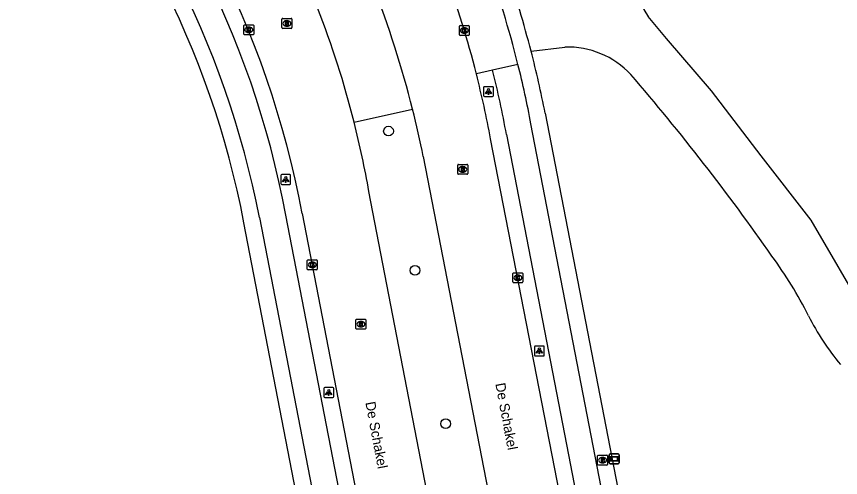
# Model space of a CAD drawing. Extents: x 156141 to 158132, y 385651 to 388399.
# Drawn here: x 156763.2 to 156845.9, y 386839.7 to 386886.1 of the extents above; entities that cross this region are included whole.
import ezdxf

# ---------------------------------------------------------------- set-up
doc = ezdxf.new("R2010")
doc.units = 0
for name, color, linetype in [('IMGEO_Boom', 7, 'Continuous'), ('IMGEO_Brandkraan', 7, 'Continuous'), ('IMGEO_Fietspad_gesloten', 7, 'Continuous'), ('IMGEO_Kolk', 7, 'Continuous'), ('IMGEO_Lichtpunt', 7, 'Continuous'), ('IMGEO_Openbare_ruimte_label', 7, 'Continuous'), ('IMGEO_Rijbaan_lokaal_gesloten', 7, 'Continuous'), ('IMGEO_Rijbaan_lokaal_open', 7, 'Continuous'), ('IMGEO_Rioolput', 7, 'Continuous'), ('IMGEO_Verklikker', 7, 'Continuous'), ('IMGEO_Voetpad_open', 7, 'Continuous')]:
    doc.layers.add(name, color=color, linetype=linetype)

msp = doc.modelspace()

# ---------------------------------------------------------------- linework, layer by layer
at = {"layer": 'IMGEO_Boom'}
for centre in [(156800.541, 386874.566), (156803.195, 386860.57), (156806.282, 386845.15)]:
    msp.add_circle(centre, 0.489, dxfattribs=at)
at = {"layer": 'IMGEO_Brandkraan'}
for p, q in [((156821.54, 386841.068), (156821.54, 386841.92)), ((156821.615, 386841.994), (156822.467, 386841.994)), ((156822.028, 386841.774), (156822.053, 386841.774)), ((156822.541, 386841.92), (156822.541, 386841.068)), ((156822.467, 386840.994), (156821.615, 386840.994)), ((156822.051, 386841.214), (156822.026, 386841.214))]:
    msp.add_line(p, q, dxfattribs=at)
for points in [[(156821.54, 386841.068), (156821.54, 386841.92)], [(156821.615, 386841.994), (156822.467, 386841.994)], [(156821.888, 386841.694), (156821.888, 386841.294), (156822.101, 386841.294)], [(156822.119, 386841.694), (156821.888, 386841.694)], [(156822.067, 386841.613), (156822.013, 386841.613), (156822.013, 386841.537)], [(156822.013, 386841.537), (156822.066, 386841.537)], [(156822.541, 386841.92), (156822.541, 386841.068)], [(156822.467, 386840.994), (156821.615, 386840.994)], [(156822.075, 386841.461), (156822.013, 386841.461), (156822.013, 386841.38)], [(156822.013, 386841.38), (156822.075, 386841.38)]]:
    msp.add_lwpolyline(points, dxfattribs=at)
for centre, radius, start, end in [((156821.617, 386841.918), 0.0765, 91.55205, 178.44795), ((156821.617, 386841.918), 0.0765, 91.55205, 178.44795), ((156822.068, 386841.575), 0.0379, 267.82845, 90.93552), ((156822.123, 386841.549), 0.145, 59.4692, 91.53667), ((156822.148, 386841.596), 0.0922, 285.51372, 58.15012), ((156822.153, 386841.404), 0.105, 301.31148, 78.98903), ((156822.465, 386841.918), 0.0765, 1.55205, 88.44795), ((156822.465, 386841.918), 0.0765, 1.55205, 88.44795), ((156821.617, 386841.07), 0.0765, 181.55205, 268.44795), ((156821.617, 386841.07), 0.0765, 181.55205, 268.44795), ((156822.076, 386841.42), 0.0404, 269.87594, 90.50774), ((156822.107, 386841.545), 0.251, 268.66757, 293.53466), ((156822.465, 386841.07), 0.0765, 271.55205, 358.44795), ((156822.465, 386841.07), 0.0765, 271.55205, 358.44795)]:
    msp.add_arc(centre, radius, start, end, dxfattribs=at)
for centre, major_axis, ratio, start_param, end_param in [((156822.027, 386841.494), (-0.387, 0.002), 0.722429, 4.712389, 7.853982), ((156822.052, 386841.494), (-0.39, 0.002), 0.717154, 1.570796, 4.712389)]:
    msp.add_ellipse(centre, major_axis=major_axis, ratio=ratio, start_param=start_param, end_param=end_param, dxfattribs=at)
at = {"layer": 'IMGEO_Fietspad_gesloten'}
for points in [[(156831.327, 386790.024), (156827.767, 386808.488), (156814.851, 386875.299)], [(156812.389, 386874.233), (156825.217, 386807.909)], [(156787.566, 386865.893), (156800.014, 386801.586)], [(156802.323, 386803.676), (156790.238, 386866.122)]]:
    msp.add_lwpolyline(points, dxfattribs=at)
for centre, radius, start, end in [((156697.735, 386848.719), 94.126, 10.65483, 44.23031), ((156696.985, 386848.39), 92.256, 10.93627, 43.98113), ((156711.691, 386855.855), 104.977, 10.67398, 14.01163), ((156710.398, 386855.539), 103.69, 10.38669, 14.03443)]:
    msp.add_arc(centre, radius, start, end, dxfattribs=at)
at = {"layer": 'IMGEO_Kolk'}
for p, q in [((156786.008, 386884.32), (156786.008, 386885.172)), ((156786.083, 386885.246), (156786.935, 386885.246)), ((156786.496, 386885.026), (156786.521, 386885.026)), ((156787.009, 386885.172), (156787.009, 386884.32)), ((156807.654, 386884.252), (156807.654, 386885.104)), ((156807.729, 386885.178), (156808.581, 386885.178)), ((156808.142, 386884.958), (156808.167, 386884.958)), ((156808.655, 386885.104), (156808.655, 386884.252)), ((156786.935, 386884.246), (156786.083, 386884.246)), ((156786.519, 386884.466), (156786.494, 386884.466)), ((156808.581, 386884.178), (156807.729, 386884.178)), ((156808.165, 386884.398), (156808.14, 386884.398)), ((156792.385, 386860.705), (156792.385, 386861.557)), ((156792.46, 386861.631), (156793.312, 386861.631)), ((156792.873, 386861.411), (156792.898, 386861.411)), ((156793.386, 386861.557), (156793.386, 386860.705)), ((156793.312, 386860.631), (156792.46, 386860.631)), ((156792.896, 386860.851), (156792.871, 386860.851)), ((156813.032, 386859.401), (156813.032, 386860.253)), ((156813.107, 386860.327), (156813.959, 386860.327)), ((156813.52, 386860.107), (156813.545, 386860.107)), ((156814.033, 386860.253), (156814.033, 386859.401)), ((156813.959, 386859.327), (156813.107, 386859.327)), ((156813.543, 386859.547), (156813.518, 386859.547))]:
    msp.add_line(p, q, dxfattribs=at)
for points in [[(156786.008, 386884.32), (156786.008, 386885.172)], [(156786.083, 386885.246), (156786.935, 386885.246)], [(156786.329, 386884.946), (156786.452, 386884.946), (156786.452, 386884.795), (156786.582, 386884.946), (156786.746, 386884.946), (156786.6, 386884.795), (156786.753, 386884.546), (156786.601, 386884.546), (156786.516, 386884.71), (156786.452, 386884.643), (156786.452, 386884.546), (156786.329, 386884.546), (156786.329, 386884.946)], [(156787.009, 386885.172), (156787.009, 386884.32)], [(156807.654, 386884.252), (156807.654, 386885.104)], [(156807.729, 386885.178), (156808.581, 386885.178)], [(156807.975, 386884.878), (156808.098, 386884.878), (156808.098, 386884.727), (156808.228, 386884.878), (156808.392, 386884.878), (156808.246, 386884.727), (156808.399, 386884.478), (156808.247, 386884.478), (156808.162, 386884.642), (156808.098, 386884.575), (156808.098, 386884.478), (156807.975, 386884.478), (156807.975, 386884.878)], [(156808.655, 386885.104), (156808.655, 386884.252)], [(156786.935, 386884.246), (156786.083, 386884.246)], [(156808.581, 386884.178), (156807.729, 386884.178)], [(156792.385, 386860.705), (156792.385, 386861.557)], [(156792.46, 386861.631), (156793.312, 386861.631)], [(156793.386, 386861.557), (156793.386, 386860.705)], [(156793.312, 386860.631), (156792.46, 386860.631)], [(156792.706, 386861.331), (156792.829, 386861.331), (156792.829, 386861.18), (156792.959, 386861.331), (156793.123, 386861.331), (156792.977, 386861.18), (156793.13, 386860.931), (156792.978, 386860.931), (156792.893, 386861.095), (156792.829, 386861.028), (156792.829, 386860.931), (156792.706, 386860.931), (156792.706, 386861.331)], [(156813.032, 386859.401), (156813.032, 386860.253)], [(156813.107, 386860.327), (156813.959, 386860.327)], [(156813.353, 386860.027), (156813.476, 386860.027), (156813.476, 386859.876), (156813.606, 386860.027), (156813.77, 386860.027), (156813.624, 386859.876), (156813.777, 386859.627), (156813.625, 386859.627), (156813.54, 386859.791), (156813.476, 386859.724), (156813.476, 386859.627), (156813.353, 386859.627), (156813.353, 386860.027)], [(156814.033, 386860.253), (156814.033, 386859.401)], [(156813.959, 386859.327), (156813.107, 386859.327)]]:
    msp.add_lwpolyline(points, dxfattribs=at)
for centre, start, end in [((156786.085, 386885.17), 91.55205, 178.44795), ((156786.085, 386885.17), 91.55205, 178.44795), ((156786.933, 386885.17), 1.55205, 88.44795), ((156786.933, 386885.17), 1.55205, 88.44795), ((156807.731, 386885.102), 91.55205, 178.44795), ((156807.731, 386885.102), 91.55205, 178.44795), ((156808.579, 386885.102), 1.55205, 88.44795), ((156808.579, 386885.102), 1.55205, 88.44795), ((156786.085, 386884.322), 181.55205, 268.44795), ((156786.085, 386884.322), 181.55205, 268.44795), ((156786.933, 386884.322), 271.55205, 358.44795), ((156786.933, 386884.322), 271.55205, 358.44795), ((156807.731, 386884.254), 181.55205, 268.44795), ((156807.731, 386884.254), 181.55205, 268.44795), ((156808.579, 386884.254), 271.55205, 358.44795), ((156808.579, 386884.254), 271.55205, 358.44795), ((156792.462, 386861.555), 91.55205, 178.44795), ((156792.462, 386861.555), 91.55205, 178.44795), ((156793.31, 386861.555), 1.55205, 88.44795), ((156793.31, 386861.555), 1.55205, 88.44795), ((156792.462, 386860.707), 181.55205, 268.44795), ((156792.462, 386860.707), 181.55205, 268.44795), ((156793.31, 386860.707), 271.55205, 358.44795), ((156793.31, 386860.707), 271.55205, 358.44795), ((156813.109, 386860.251), 91.55205, 178.44795), ((156813.109, 386860.251), 91.55205, 178.44795), ((156813.957, 386860.251), 1.55205, 88.44795), ((156813.957, 386860.251), 1.55205, 88.44795), ((156813.109, 386859.403), 181.55205, 268.44795), ((156813.109, 386859.403), 181.55205, 268.44795), ((156813.957, 386859.403), 271.55205, 358.44795), ((156813.957, 386859.403), 271.55205, 358.44795)]:
    msp.add_arc(centre, 0.0765, start, end, dxfattribs=at)
for centre, major_axis, ratio, start_param, end_param in [((156786.495, 386884.746), (-0.387, 0.002), 0.722429, 4.712389, 7.853982), ((156786.52, 386884.746), (-0.39, 0.002), 0.717154, 1.570796, 4.712389), ((156808.141, 386884.678), (-0.387, 0.002), 0.722429, 4.712389, 7.853982), ((156808.166, 386884.678), (-0.39, 0.002), 0.717154, 1.570796, 4.712389), ((156792.872, 386861.131), (-0.387, 0.002), 0.722429, 4.712389, 7.853982), ((156792.897, 386861.131), (-0.39, 0.002), 0.717154, 1.570796, 4.712389), ((156813.519, 386859.827), (-0.387, 0.002), 0.722429, 4.712389, 7.853982), ((156813.544, 386859.827), (-0.39, 0.002), 0.717154, 1.570796, 4.712389)]:
    msp.add_ellipse(centre, major_axis=major_axis, ratio=ratio, start_param=start_param, end_param=end_param, dxfattribs=at)
at = {"layer": 'IMGEO_Lichtpunt'}
for p, q in [((156810.085, 386878.94), (156810.085, 386878.133)), ((156810.085, 386878.94), (156810.085, 386878.133)), ((156810.987, 386879.035), (156810.179, 386879.035)), ((156810.987, 386879.035), (156810.179, 386879.035)), ((156811.081, 386878.133), (156811.081, 386878.94)), ((156811.081, 386878.133), (156811.081, 386878.94)), ((156810.179, 386878.039), (156810.987, 386878.039)), ((156810.179, 386878.039), (156810.987, 386878.039)), ((156789.714, 386870.102), (156789.714, 386869.295)), ((156789.714, 386870.102), (156789.714, 386869.295)), ((156790.616, 386870.197), (156789.808, 386870.197)), ((156790.616, 386870.197), (156789.808, 386870.197)), ((156790.71, 386869.295), (156790.71, 386870.102)), ((156790.71, 386869.295), (156790.71, 386870.102)), ((156789.808, 386869.201), (156790.616, 386869.201)), ((156789.808, 386869.201), (156790.616, 386869.201)), ((156815.193, 386852.869), (156815.193, 386852.062)), ((156815.193, 386852.869), (156815.193, 386852.062)), ((156816.095, 386852.964), (156815.287, 386852.964)), ((156816.095, 386852.964), (156815.287, 386852.964)), ((156816.189, 386852.062), (156816.189, 386852.869)), ((156816.189, 386852.062), (156816.189, 386852.869)), ((156815.287, 386851.968), (156816.095, 386851.968)), ((156815.287, 386851.968), (156816.095, 386851.968)), ((156794.038, 386848.696), (156794.038, 386847.889)), ((156794.038, 386848.696), (156794.038, 386847.889)), ((156794.94, 386848.791), (156794.132, 386848.791)), ((156794.94, 386848.791), (156794.132, 386848.791)), ((156795.034, 386847.889), (156795.034, 386848.696)), ((156795.034, 386847.889), (156795.034, 386848.696)), ((156794.132, 386847.795), (156794.94, 386847.795)), ((156794.132, 386847.795), (156794.94, 386847.795))]:
    msp.add_line(p, q, dxfattribs=at)
for points in [[(156810.459, 386878.604), (156810.498, 386878.576), (156810.31, 386878.314), (156810.272, 386878.341), (156810.459, 386878.604)], [(156810.561, 386878.556), (156810.608, 386878.556), (156810.608, 386878.234), (156810.561, 386878.234), (156810.561, 386878.556)], [(156810.671, 386878.576), (156810.709, 386878.603), (156810.896, 386878.341), (156810.857, 386878.313), (156810.671, 386878.576)], [(156790.088, 386869.766), (156790.127, 386869.738), (156789.939, 386869.476), (156789.901, 386869.503), (156790.088, 386869.766)], [(156790.19, 386869.718), (156790.237, 386869.718), (156790.237, 386869.396), (156790.19, 386869.396), (156790.19, 386869.718)], [(156790.3, 386869.738), (156790.338, 386869.765), (156790.525, 386869.503), (156790.486, 386869.475), (156790.3, 386869.738)], [(156815.567, 386852.533), (156815.606, 386852.505), (156815.418, 386852.243), (156815.38, 386852.27), (156815.567, 386852.533)], [(156815.669, 386852.485), (156815.716, 386852.485), (156815.716, 386852.163), (156815.669, 386852.163), (156815.669, 386852.485)], [(156815.779, 386852.505), (156815.817, 386852.532), (156816.004, 386852.27), (156815.965, 386852.242), (156815.779, 386852.505)], [(156794.412, 386848.36), (156794.451, 386848.332), (156794.263, 386848.07), (156794.225, 386848.097), (156794.412, 386848.36)], [(156794.514, 386848.312), (156794.561, 386848.312), (156794.561, 386847.99), (156794.514, 386847.99), (156794.514, 386848.312)], [(156794.624, 386848.332), (156794.662, 386848.359), (156794.849, 386848.097), (156794.81, 386848.069), (156794.624, 386848.332)]]:
    msp.add_lwpolyline(points, dxfattribs=at)
for centre in [(156810.584, 386878.738), (156790.213, 386869.9), (156815.692, 386852.667), (156794.537, 386848.494)]:
    msp.add_circle(centre, 0.0994, dxfattribs=at)
for centre, start, end in [((156810.179, 386878.94), 90, 180), ((156810.179, 386878.94), 90, 180), ((156810.987, 386878.94), 0, 90), ((156810.987, 386878.94), 0, 90), ((156810.179, 386878.133), 180, 270), ((156810.179, 386878.133), 180, 270), ((156810.987, 386878.133), 270, 0), ((156810.987, 386878.133), 270, 360), ((156789.808, 386870.102), 90, 180), ((156789.808, 386870.102), 90, 180), ((156790.616, 386870.102), 0, 90), ((156790.616, 386870.102), 0, 90), ((156789.808, 386869.295), 180, 270), ((156789.808, 386869.295), 180, 270), ((156790.616, 386869.295), 270, 0), ((156790.616, 386869.295), 270, 360), ((156815.287, 386852.869), 90, 180), ((156815.287, 386852.869), 90, 180), ((156816.095, 386852.869), 0, 90), ((156816.095, 386852.869), 0, 90), ((156815.287, 386852.062), 180, 270), ((156815.287, 386852.062), 180, 270), ((156816.095, 386852.062), 270, 0), ((156816.095, 386852.062), 270, 360), ((156794.132, 386848.696), 90, 180), ((156794.132, 386848.696), 90, 180), ((156794.94, 386848.696), 0, 90), ((156794.94, 386848.696), 0, 90), ((156794.132, 386847.889), 180, 270), ((156794.132, 386847.889), 180, 270), ((156794.94, 386847.889), 270, 0), ((156794.94, 386847.889), 270, 360)]:
    msp.add_arc(centre, 0.0946, start, end, dxfattribs=at)
at = {"layer": 'IMGEO_Rijbaan_lokaal_gesloten'}
for points in [[(156823.671, 386807.616), (156810.794, 386873.793)], [(156804.032, 386872.006), (156816.188, 386809.335)], [(156810.203, 386808.253), (156798.576, 386868.484)], [(156791.866, 386866.288), (156803.921, 386803.962)]]:
    msp.add_lwpolyline(points, dxfattribs=at)
for centre, radius, start, end in [((156697.171, 386848.541), 96.344, 10.61478, 43.91153), ((156709.441, 386854.985), 103.083, 14.22096, 20.0977), ((156702.571, 386851.552), 103.502, 14.09743, 21.30467), ((156703.2, 386851.742), 96.836, 14.18776, 21.33413), ((156709.21, 386854.93), 103.32, 10.51953, 14.21947), ((156702.267, 386851.482), 103.814, 11.40228, 14.09375), ((156702.296, 386851.571), 97.754, 9.96341, 14.15559)]:
    msp.add_arc(centre, radius, start, end, dxfattribs=at)
at = {"layer": 'IMGEO_Rijbaan_lokaal_open'}
for points in [[(156848.662, 386855.9), (156842.982, 386865.604), (156837.967, 386872.098), (156832.982, 386878.607), (156828.456, 386883.873), (156826.636, 386886.092)], [(156814.86, 386882.608), (156818.263, 386883.015)], [(156813.544, 386881.272), (156810.993, 386880.684)], [(156810.993, 386880.684), (156809.365, 386880.309)], [(156797.082, 386875.477), (156802.956, 386876.762)]]:
    msp.add_lwpolyline(points, dxfattribs=at)
for centre, radius, start, end in [((156830.262, 386888.804), 4.528, 133.86718, 216.79599), ((156710.397, 386855.529), 106.31, 14.0134, 19.91092), ((156711.519, 386855.915), 106.733, 14.4829, 19.05231), ((156818.511, 386874.287), 8.732, 43.19971, 91.62579), ((156650.564, 386730.314), 229.935, 34.94261, 40.70341), ((156805.973, 386837.682), 41.058, 26.50354, 36.33706), ((156866.609, 386868.18), 26.816, 207.00334, 219.5816)]:
    msp.add_arc(centre, radius, start, end, dxfattribs=at)
at = {"layer": 'IMGEO_Rioolput'}
for p, q in [((156789.834, 386884.968), (156789.834, 386885.82)), ((156789.909, 386885.894), (156790.761, 386885.894)), ((156790.322, 386885.674), (156790.347, 386885.674)), ((156790.835, 386885.82), (156790.835, 386884.968)), ((156790.761, 386884.894), (156789.909, 386884.894)), ((156790.345, 386885.114), (156790.32, 386885.114)), ((156807.496, 386870.298), (156807.496, 386871.15)), ((156807.571, 386871.224), (156808.423, 386871.224)), ((156808.007, 386870.444), (156807.982, 386870.444)), ((156807.984, 386871.004), (156808.009, 386871.004)), ((156808.497, 386871.15), (156808.497, 386870.298)), ((156808.423, 386870.224), (156807.571, 386870.224)), ((156797.265, 386854.74), (156797.265, 386855.592)), ((156797.34, 386855.666), (156798.192, 386855.666)), ((156798.266, 386855.592), (156798.266, 386854.74)), ((156797.776, 386854.886), (156797.751, 386854.886)), ((156797.753, 386855.446), (156797.778, 386855.446)), ((156798.192, 386854.666), (156797.34, 386854.666))]:
    msp.add_line(p, q, dxfattribs=at)
for points in [[(156789.834, 386884.968), (156789.834, 386885.82)], [(156789.909, 386885.894), (156790.761, 386885.894)], [(156790.423, 386885.592), (156790.171, 386885.594), (156790.171, 386885.194)], [(156790.171, 386885.194), (156790.295, 386885.194), (156790.295, 386885.356), (156790.306, 386885.356)], [(156790.349, 386885.513), (156790.295, 386885.513), (156790.295, 386885.432)], [(156790.295, 386885.432), (156790.347, 386885.432)], [(156790.835, 386885.82), (156790.835, 386884.968)], [(156790.761, 386884.894), (156789.909, 386884.894)], [(156790.353, 386885.327), (156790.424, 386885.194), (156790.564, 386885.194), (156790.499, 386885.32)], [(156807.496, 386870.298), (156807.496, 386871.15)], [(156807.571, 386871.224), (156808.423, 386871.224)], [(156808.085, 386870.922), (156807.833, 386870.924), (156807.833, 386870.524)], [(156807.833, 386870.524), (156807.957, 386870.524), (156807.957, 386870.686), (156807.968, 386870.686)], [(156808.011, 386870.843), (156807.957, 386870.843), (156807.957, 386870.762)], [(156807.957, 386870.762), (156808.009, 386870.762)], [(156808.015, 386870.657), (156808.086, 386870.524), (156808.226, 386870.524), (156808.161, 386870.65)], [(156808.497, 386871.15), (156808.497, 386870.298)], [(156808.423, 386870.224), (156807.571, 386870.224)], [(156797.265, 386854.74), (156797.265, 386855.592)], [(156797.34, 386855.666), (156798.192, 386855.666)], [(156798.266, 386855.592), (156798.266, 386854.74)], [(156797.854, 386855.364), (156797.602, 386855.366), (156797.602, 386854.966)], [(156797.602, 386854.966), (156797.726, 386854.966), (156797.726, 386855.128), (156797.737, 386855.128)], [(156797.78, 386855.285), (156797.726, 386855.285), (156797.726, 386855.204)], [(156797.726, 386855.204), (156797.778, 386855.204)], [(156797.784, 386855.099), (156797.855, 386854.966), (156797.995, 386854.966), (156797.93, 386855.092)], [(156798.192, 386854.666), (156797.34, 386854.666)]]:
    msp.add_lwpolyline(points, dxfattribs=at)
for centre, radius, start, end in [((156789.911, 386885.818), 0.0765, 91.55205, 178.44795), ((156789.911, 386885.818), 0.0765, 91.55205, 178.44795), ((156790.305, 386885.303), 0.0533, 26.02933, 88.69889), ((156790.331, 386885.621), 0.19, 274.7715, 282.96867), ((156790.355, 386885.417), 0.0964, 77.00612, 93.18647), ((156790.369, 386885.474), 0.0378, 276.66336, 79.67722), ((156790.422, 386885.482), 0.109, 350.36119, 89.41601), ((156790.42, 386885.482), 0.112, 277.58423, 350.98172), ((156790.404, 386885.267), 0.108, 29.51342, 73.79051), ((156790.759, 386885.818), 0.0765, 1.55205, 88.44795), ((156790.759, 386885.818), 0.0765, 1.55205, 88.44795), ((156789.911, 386884.97), 0.0765, 181.55205, 268.44795), ((156789.911, 386884.97), 0.0765, 181.55205, 268.44795), ((156790.759, 386884.97), 0.0765, 271.55205, 358.44795), ((156790.759, 386884.97), 0.0765, 271.55205, 358.44795), ((156807.573, 386871.148), 0.0765, 91.55205, 178.44795), ((156807.573, 386871.148), 0.0765, 91.55205, 178.44795), ((156807.967, 386870.633), 0.0533, 26.02933, 88.69889), ((156807.993, 386870.951), 0.19, 274.7715, 282.96867), ((156808.017, 386870.747), 0.0964, 77.00612, 93.18647), ((156808.031, 386870.804), 0.0378, 276.66336, 79.67722), ((156808.084, 386870.812), 0.109, 350.36119, 89.41601), ((156808.082, 386870.812), 0.112, 277.58423, 350.98172), ((156808.066, 386870.597), 0.108, 29.51342, 73.79051), ((156808.421, 386871.148), 0.0765, 1.55205, 88.44795), ((156808.421, 386871.148), 0.0765, 1.55205, 88.44795), ((156807.573, 386870.3), 0.0765, 181.55205, 268.44795), ((156807.573, 386870.3), 0.0765, 181.55205, 268.44795), ((156808.421, 386870.3), 0.0765, 271.55205, 358.44795), ((156808.421, 386870.3), 0.0765, 271.55205, 358.44795), ((156797.342, 386855.59), 0.0765, 91.55205, 178.44795), ((156797.342, 386855.59), 0.0765, 91.55205, 178.44795), ((156798.19, 386855.59), 0.0765, 1.55205, 88.44795), ((156798.19, 386855.59), 0.0765, 1.55205, 88.44795), ((156797.342, 386854.742), 0.0765, 181.55205, 268.44795), ((156797.342, 386854.742), 0.0765, 181.55205, 268.44795), ((156797.736, 386855.075), 0.0533, 26.02933, 88.69889), ((156797.762, 386855.393), 0.19, 274.7715, 282.96867), ((156797.786, 386855.189), 0.0964, 77.00612, 93.18647), ((156797.8, 386855.246), 0.0378, 276.66336, 79.67722), ((156797.853, 386855.254), 0.109, 350.36119, 89.41601), ((156797.851, 386855.254), 0.112, 277.58423, 350.98172), ((156797.835, 386855.039), 0.108, 29.51342, 73.79051), ((156798.19, 386854.742), 0.0765, 271.55205, 358.44795), ((156798.19, 386854.742), 0.0765, 271.55205, 358.44795)]:
    msp.add_arc(centre, radius, start, end, dxfattribs=at)
for centre, major_axis, ratio, start_param, end_param in [((156790.321, 386885.394), (-0.387, 0.002), 0.722429, 4.712389, 7.853982), ((156790.346, 386885.394), (-0.39, 0.002), 0.717154, 1.570796, 4.712389), ((156807.983, 386870.724), (-0.387, 0.002), 0.722429, 4.712389, 7.853982), ((156808.008, 386870.724), (-0.39, 0.002), 0.717154, 1.570796, 4.712389), ((156797.752, 386855.166), (-0.387, 0.002), 0.722429, 4.712389, 7.853982), ((156797.777, 386855.166), (-0.39, 0.002), 0.717154, 1.570796, 4.712389)]:
    msp.add_ellipse(centre, major_axis=major_axis, ratio=ratio, start_param=start_param, end_param=end_param, dxfattribs=at)
at = {"layer": 'IMGEO_Verklikker'}
for p, q in [((156822.717, 386841.217), (156822.717, 386842.017)), ((156822.717, 386842.017), (156822.717, 386841.217)), ((156822.817, 386842.117), (156823.607, 386842.117)), ((156823.607, 386842.117), (156822.817, 386842.117)), ((156823.707, 386842.017), (156823.707, 386841.217)), ((156823.707, 386841.217), (156823.707, 386842.017)), ((156823.607, 386841.117), (156822.817, 386841.117)), ((156822.817, 386841.117), (156823.607, 386841.117))]:
    msp.add_line(p, q, dxfattribs=at)
for points in [[(156822.818, 386841.849), (156823.606, 386841.849), (156823.606, 386841.385), (156822.818, 386841.385), (156822.818, 386841.849)], [(156822.883, 386841.784), (156822.883, 386841.45), (156823.541, 386841.45), (156823.541, 386841.784), (156822.883, 386841.784)]]:
    msp.add_lwpolyline(points, dxfattribs=at)
for centre, start, end in [((156822.817, 386842.017), 90, 180), ((156822.817, 386842.017), 90, 180), ((156823.607, 386842.017), 0, 90), ((156823.607, 386842.017), 360, 90), ((156822.817, 386841.217), 180, 270), ((156822.817, 386841.217), 180, 270), ((156823.607, 386841.217), 270, 0), ((156823.607, 386841.217), 270, 0)]:
    msp.add_arc(centre, 0.1, start, end, dxfattribs=at)
at = {"layer": 'IMGEO_Voetpad_open'}
for points in [[(156816.275, 386876.382), (156829.265, 386809.226), (156830.26, 386804.068), (156832.909, 386790.329)], [(156799.862, 386793.67), (156786.023, 386865.361)]]:
    msp.add_lwpolyline(points, dxfattribs=at)
for centre, radius, start, end in [((156696.676, 386848.251), 90.971, 10.84103, 44.16358), ((156711.598, 386855.865), 106.669, 11.08926, 14.51927)]:
    msp.add_arc(centre, radius, start, end, dxfattribs=at)

# ---------------------------------------------------------------- texts
at = {"layer": 'IMGEO_Openbare_ruimte_label'}
for p in [(156811.263, 386849.165), (156798.21, 386847.283)]:
    msp.add_text('De Schakel', height=1, rotation=280.65836, dxfattribs=at).set_placement(p)

doc.saveas('drawing.dxf')
